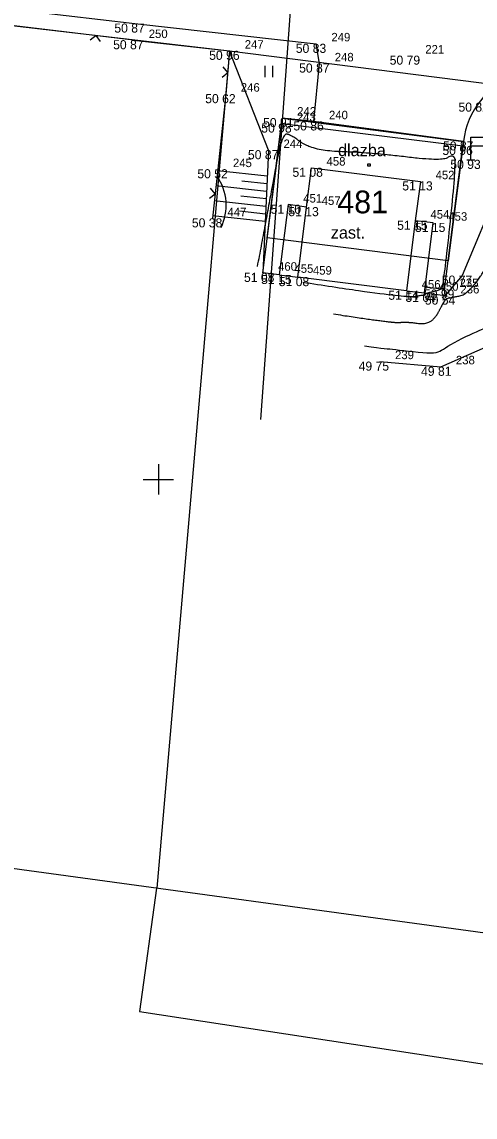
# Model space of a CAD drawing. Extents: x -704057 to -703795, y -1008732 to -1008584.
# Drawn here: x -703954.51 to -703939.55, y -1008696.05 to -1008659.9 of the extents above; entities that cross this region are included whole.
import ezdxf

# ---------------------------------------------------------------- set-up
doc = ezdxf.new("R2010")
doc.units = 0
for name, color, linetype in [('Z_body', 7, 'Continuous'), ('Z_body_cisla', 7, 'Continuous'), ('Z_body_vysky', 7, 'Continuous'), ('Z_budovy', 7, 'Continuous'), ('Z_chodnik', 7, 'Continuous'), ('Z_dopravni_znaceni', 7, 'Continuous'), ('Z_hekt_sit', 7, 'Continuous'), ('Z_katastr_cisla_stavebni', 7, 'Continuous'), ('Z_katastr_hranice', 7, 'Continuous'), ('Z_katastr_vnitrni_kresba', 7, 'Continuous'), ('Z_katastr_znacky', 7, 'Continuous'), ('Z_komunikace_zpevn_pl', 7, 'Continuous'), ('Z_obruby', 7, 'Continuous'), ('Z_oploceni', 7, 'Continuous'), ('Z_popis', 7, 'Continuous'), ('Z_rozhrani_zpevn', 7, 'Continuous'), ('Z_site_nadz_nerozl', 7, 'Continuous'), ('Z_teren_hrany_paty', 7, 'Continuous'), ('Z_vrstevnice_hlavni', 7, 'Continuous'), ('Z_vrstevnice_popis', 7, 'Continuous'), ('Z_vrstevnice_vedlejsi', 7, 'Continuous'), ('Z_vstupy', 7, 'Continuous')]:
    doc.layers.add(name, color=color, linetype=linetype)

# ---------------------------------------------------------------- blocks, each defined once
blk = doc.blocks.new('POINT_DISPLAY')
blk.add_line((0, 0), (0, 0))
blk = doc.blocks.new('Z212')
for p, q in [((-0.17, 0.17), (0, 0)), ((0, 0), (0.17, 0.17))]:
    blk.add_line(p, q)
blk = doc.blocks.new('Z524')
for p, q in [((0, 0), (0, 0.75)), ((0, 0.75), (0.5, 0.75)), ((0.5, 0.75), (0.5, 0.45)), ((0.5, 0.45), (0, 0.45)), ((-0.13, 0), (0.13, 0))]:
    blk.add_line(p, q)
blk = doc.blocks.new('Z402')
for p, q in [((-0.03, 0.03), (0.05, 0.03)), ((-0.03, -0.05), (-0.03, 0.03)), ((0.05, 0.03), (0.05, -0.05)), ((0.05, -0.05), (-0.03, -0.05))]:
    blk.add_line(p, q)
blk = doc.blocks.new('Z306')
for p, q in [((-0.13, 0.17), (-0.13, -0.2)), ((0.13, 0.17), (0.13, -0.2))]:
    blk.add_line(p, q)

msp = doc.modelspace()

# ---------------------------------------------------------------- linework, layer by layer
at = {"layer": 'Z_budovy'}
for p, q in [((-703945.11, -1008666.01), (-703944.95, -1008664.71)), ((-703944.95, -1008664.71), (-703941.35, -1008665.16)), ((-703941.35, -1008665.16), (-703941.52, -1008666.46)), ((-703945.4, -1008668.32), (-703945.11, -1008666.01)), ((-703941.52, -1008666.46), (-703941.81, -1008668.77)), ((-703941.81, -1008668.77), (-703945.4, -1008668.32))]:
    msp.add_line(p, q, dxfattribs=at)
at = {"layer": 'Z_chodnik'}
for p, q in [((-703945.92, -1008663.07), (-703945.93, -1008663.25)), ((-703944.87, -1008663.18), (-703945.92, -1008663.07)), ((-703940.56, -1008668.73), (-703939.95, -1008663.99)), ((-703939.95, -1008663.99), (-703939.93, -1008663.84)), ((-703940.56, -1008668.73), (-703941.2, -1008668.65))]:
    msp.add_line(p, q, dxfattribs=at)
at = {"layer": 'Z_hekt_sit'}
for p, q in [((-703950, -1008674.5), (-703950, -1008675.5)), ((-703950.5, -1008675), (-703949.5, -1008675))]:
    msp.add_line(p, q, dxfattribs=at)
at = {"layer": 'Z_katastr_hranice'}
for p, q in [((-703977.9, -1008657.35), (-703947.65, -1008660.85)), ((-703947.65, -1008660.85), (-703950.05, -1008688.49)), ((-703947.65, -1008660.85), (-703907.73, -1008665.91)), ((-703946.41, -1008667.03), (-703945.92, -1008663.07)), ((-703945.92, -1008663.07), (-703939.93, -1008663.84)), ((-703939.93, -1008663.84), (-703940.44, -1008667.78)), ((-703940.44, -1008667.78), (-703946.41, -1008667.03)), ((-703972.28, -1008685.45), (-703894.62, -1008696.05))]:
    msp.add_line(p, q, dxfattribs=at)
at = {"layer": 'Z_katastr_vnitrni_kresba'}
for p, q in [((-703950.06, -1008688.49), (-703950.63, -1008692.56)), ((-703950.63, -1008692.56), (-703938.7, -1008694.39))]:
    msp.add_line(p, q, dxfattribs=at)
at = {"layer": 'Z_komunikace_zpevn_pl'}
for p, q in [((-703960.94, -1008658.77), (-703950.78, -1008659.95)), ((-703950.78, -1008659.95), (-703944.79, -1008660.62)), ((-703944.68, -1008661.27), (-703944.79, -1008660.62)), ((-703944.87, -1008663.18), (-703944.68, -1008661.27)), ((-703939.93, -1008663.84), (-703944.87, -1008663.18))]:
    msp.add_line(p, q, dxfattribs=at)
msp.add_arc((-703937.28, -1008664.15), 2.666, 110.1364, 173.2493, dxfattribs=at)
at = {"layer": 'Z_obruby'}
msp.add_line((-703945.93, -1008663.25), (-703939.95, -1008663.99), dxfattribs=at)
at = {"layer": 'Z_oploceni'}
for p, q in [((-703950.82, -1008660.5), (-703955.62, -1008659.92)), ((-703947.65, -1008660.85), (-703947.78, -1008662.28)), ((-703947.78, -1008662.28), (-703948.04, -1008664.76)), ((-703948.04, -1008664.76), (-703948.22, -1008666.38))]:
    msp.add_line(p, q, dxfattribs=at)
at = {"layer": 'Z_rozhrani_zpevn'}
for p, q in [((-703946.55, -1008668.18), (-703945.93, -1008663.25)), ((-703945.72, -1008665.93), (-703946.01, -1008668.25)), ((-703945.11, -1008666.01), (-703945.72, -1008665.93)), ((-703940.93, -1008666.53), (-703941.52, -1008666.46)), ((-703941.22, -1008668.84), (-703940.93, -1008666.53)), ((-703946.01, -1008668.25), (-703946.55, -1008668.18)), ((-703946.01, -1008668.25), (-703945.4, -1008668.32)), ((-703941.81, -1008668.77), (-703941.22, -1008668.84)), ((-703941.22, -1008668.84), (-703940.53, -1008668.93)), ((-703940.53, -1008668.93), (-703940.56, -1008668.73))]:
    msp.add_line(p, q, dxfattribs=at)
at = {"layer": 'Z_site_nadz_nerozl'}
msp.add_line((-703944.98, -1008650.29), (-703946.63, -1008673.02), dxfattribs=at)
at = {"layer": 'Z_teren_hrany_paty'}
for p, q in [((-703946.37, -1008664.13), (-703947.65, -1008660.85)), ((-703938.08, -1008663.72), (-703939.97, -1008668.27)), ((-703946.37, -1008664.13), (-703946.55, -1008668.18)), ((-703946.41, -1008664.99), (-703948.05, -1008664.81)), ((-703946.43, -1008665.49), (-703948.1, -1008665.31)), ((-703946.42, -1008665.24), (-703947.25, -1008665.15)), ((-703946.45, -1008665.99), (-703948.16, -1008665.8)), ((-703946.44, -1008665.74), (-703947.28, -1008665.65)), ((-703946.46, -1008666.24), (-703947.32, -1008666.15)), ((-703946.48, -1008666.49), (-703948.21, -1008666.3)), ((-703939.97, -1008668.27), (-703940.53, -1008668.93)), ((-703940.68, -1008671.28), (-703938.83, -1008670.47)), ((-703942.69, -1008671.11), (-703940.68, -1008671.28))]:
    msp.add_line(p, q, dxfattribs=at)
at = {"layer": 'Z_vrstevnice_hlavni'}
msp.add_open_spline([(-703945.237, -1008668.488), (-703941.899, -1008669.006), (-703941.266, -1008668.91), (-703941.202, -1008668.919), (-703941.165, -1008668.847), (-703940.692, -1008668.752), (-703940.583, -1008668.593), (-703940.156, -1008664.525), (-703940.279, -1008664.265), (-703940.64, -1008664.5), (-703943.045, -1008664.207), (-703944.921, -1008664.154), (-703945.734, -1008663.542), (-703945.895, -1008663.697), (-703946.054, -1008664.236), (-703946.481, -1008666.637), (-703946.741, -1008667.974)], degree=2, dxfattribs=at)
at = {"layer": 'Z_vrstevnice_popis'}
msp.add_open_spline([(-703943.199, -1008670.586), (-703942.532, -1008670.689), (-703942.405, -1008670.67), (-703940.763, -1008670.903), (-703940.641, -1008670.668), (-703939.322, -1008670.024), (-703939.083, -1008669.981), (-703938.742, -1008669.363), (-703937.122, -1008667.441), (-703936.564, -1008666.776)], degree=3, dxfattribs=at)
at = {"layer": 'Z_vrstevnice_vedlejsi'}
msp.add_arc((-703949.434, -1008665.952), 1.671, 333.8348, 35.0599, dxfattribs=at)
msp.add_open_spline([(-703944.218, -1008669.537), (-703942.215, -1008669.847), (-703941.835, -1008669.79), (-703940.983, -1008669.911), (-703940.538, -1008669.059), (-703940.441, -1008669.011), (-703939.659, -1008668.87), (-703938.392, -1008666.573), (-703937.218, -1008665.198), (-703936.994, -1008664.158), (-703936.811, -1008663.182), (-703935.504, -1008662.788), (-703930.851, -1008662.989), (-703930.683, -1008662.945), (-703930.514, -1008662.948), (-703928.53, -1008663.14), (-703926.451, -1008662.869), (-703924.285, -1008662.962), (-703918.453, -1008660.188), (-703917.529, -1008662.583), (-703908.804, -1008661.73), (-703914.417, -1008658.58), (-703914.255, -1008657.775), (-703916.458, -1008657.408), (-703916.075, -1008656.975), (-703916.505, -1008656.883), (-703916.435, -1008655.703), (-703915.746, -1008656.007), (-703915.438, -1008656.225), (-703913.541, -1008656.36), (-703913.202, -1008656.502), (-703907.93, -1008657.256), (-703905.824, -1008657.417), (-703900.033, -1008658.024), (-703894.345, -1008658.848), (-703890.179, -1008659.57), (-703887.702, -1008659.871), (-703882.266, -1008660.175), (-703878.347, -1008660.959), (-703873.149, -1008661.531), (-703869.803, -1008661.293), (-703867.148, -1008661.514), (-703856.66, -1008662.48), (-703848.555, -1008661.935), (-703843.582, -1008661.747), (-703840.018, -1008661.713), (-703835.656, -1008661.182), (-703832.168, -1008661.259), (-703831.497, -1008661.293), (-703819.488, -1008662.346), (-703817.521, -1008662.543), (-703807.841, -1008663.114), (-703805.78, -1008663.132)], degree=2, dxfattribs=at)
at = {"layer": 'Z_vstupy'}
msp.add_line((-703950.82, -1008660.5), (-703947.65, -1008660.85), dxfattribs=at)

# ---------------------------------------------------------------- block references
at = {"layer": 'Z_body'}
for p in [(-703950.78, -1008659.95), (-703950.82, -1008660.5), (-703944.79, -1008660.62), (-703947.65, -1008660.85), (-703941.69, -1008661.01), (-703944.68, -1008661.27), (-703947.78, -1008662.28), (-703945.93, -1008663.25), (-703945.92, -1008663.07), (-703944.87, -1008663.18), (-703939.95, -1008663.99), (-703939.93, -1008663.84), (-703946.37, -1008664.13), (-703944.95, -1008664.71), (-703939.69, -1008664.45), (-703948.04, -1008664.76), (-703941.35, -1008665.16), (-703945.72, -1008665.93), (-703945.11, -1008666.01), (-703948.22, -1008666.38), (-703941.52, -1008666.46), (-703940.93, -1008666.53), (-703946.55, -1008668.18), (-703946.01, -1008668.25), (-703945.4, -1008668.32), (-703939.97, -1008668.27), (-703941.81, -1008668.77), (-703941.22, -1008668.84), (-703940.56, -1008668.73), (-703940.53, -1008668.93), (-703942.69, -1008671.11), (-703940.68, -1008671.28)]:
    msp.add_blockref('POINT_DISPLAY', p, dxfattribs=at)
at = {"layer": 'Z_dopravni_znaceni'}
msp.add_blockref('Z524', (-703939.69, -1008664.45), dxfattribs=at)
at = {"layer": 'Z_katastr_znacky'}
msp.add_blockref('Z402', (-703943.06, -1008664.61), dxfattribs=at)
at = {"layer": 'Z_oploceni'}
for p, rotation in [((-703952.06, -1008660.35), 173.1), ((-703947.71, -1008661.57), 84.8), ((-703948.13, -1008665.57), 83.7)]:
    msp.add_blockref('Z212', p, dxfattribs=dict(at, rotation=rotation))
at = {"layer": 'Z_popis'}
msp.add_blockref('Z306', (-703946.36, -1008661.52), dxfattribs=at)

# ---------------------------------------------------------------- texts
at = {"layer": 'Z_body_cisla'}
for s, p in [('250', (-703950.32, -1008660.43)), ('249', (-703944.29, -1008660.54)), ('247', (-703947.15, -1008660.78)), ('221', (-703941.19, -1008660.94)), ('248', (-703944.18, -1008661.2)), ('246', (-703947.28, -1008662.2)), ('243', (-703945.43, -1008663.18)), ('242', (-703945.42, -1008662.99)), ('240', (-703944.37, -1008663.11)), ('244', (-703945.87, -1008664.06)), ('458', (-703944.45, -1008664.64)), ('245', (-703947.54, -1008664.69)), ('452', (-703940.85, -1008665.09)), ('451', (-703945.22, -1008665.86)), ('457', (-703944.61, -1008665.94)), ('447', (-703947.72, -1008666.31)), ('454', (-703941.02, -1008666.39)), ('453', (-703940.43, -1008666.46)), ('460', (-703946.05, -1008668.11)), ('455', (-703945.51, -1008668.18)), ('459', (-703944.9, -1008668.24)), ('456', (-703941.31, -1008668.7)), ('450', (-703940.72, -1008668.77)), ('235', (-703940.06, -1008668.65)), ('236', (-703940.03, -1008668.86)), ('239', (-703942.19, -1008671.03)), ('238', (-703940.18, -1008671.2))]:
    msp.add_text(s, height=0.28, dxfattribs=at).set_placement(p)
at = {"layer": 'Z_body_vysky'}
for s, p in [('50 87', (-703951.455, -1008660.25)), ('50 87', (-703951.495, -1008660.8)), ('50 83', (-703945.465, -1008660.92)), ('50 96', (-703948.325, -1008661.15)), ('50 79', (-703942.365, -1008661.31)), ('50 87', (-703945.355, -1008661.57)), ('50 62', (-703948.455, -1008662.58)), ('50 82', (-703940.095, -1008662.86)), ('50 98', (-703946.605, -1008663.55)), ('50 91', (-703946.545, -1008663.37)), ('50 86', (-703945.545, -1008663.48)), ('50 96', (-703940.625, -1008664.29)), ('50 87', (-703940.605, -1008664.14)), ('50 87', (-703947.045, -1008664.43)), ('51 08', (-703945.575, -1008665.01)), ('50 93', (-703940.365, -1008664.75)), ('50 52', (-703948.715, -1008665.06)), ('51 13', (-703941.95, -1008665.46)), ('51 10', (-703946.295, -1008666.23)), ('51 13', (-703945.71, -1008666.31)), ('50 38', (-703948.895, -1008666.68)), ('51 15', (-703942.12, -1008666.76)), ('51 15', (-703941.53, -1008666.83)), ('51 08', (-703947.175, -1008668.48)), ('51 15', (-703946.61, -1008668.55)), ('51 08', (-703946.025, -1008668.62)), ('50 77', (-703940.645, -1008668.57)), ('51 14', (-703942.41, -1008669.07)), ('51 04', (-703941.845, -1008669.14)), ('50 99', (-703941.235, -1008669.03)), ('50 54', (-703941.205, -1008669.23)), ('49 75', (-703943.39, -1008671.41)), ('49 81', (-703941.33, -1008671.58))]:
    msp.add_text(s, height=0.3, dxfattribs=at).set_placement(p)
at = {"layer": 'Z_katastr_cisla_stavebni'}
msp.add_text('481', height=0.75, dxfattribs=at).set_placement((-703944.095, -1008666.215))
at = {"layer": 'Z_popis'}
for s, p in [('dlazba', (-703944.07, -1008664.33)), ('zast.', (-703944.31, -1008667.05))]:
    msp.add_text(s, height=0.4, dxfattribs=at).set_placement(p)

doc.saveas('drawing.dxf')
